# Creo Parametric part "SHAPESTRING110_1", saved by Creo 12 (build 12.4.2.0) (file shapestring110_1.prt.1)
Units: Custom; MM, KILOGRAM, SECS

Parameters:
  PTC_WM_ITERATION = "0"
  PTC_WM_VERSION = "-.0"
  PTC_WM_LIFECYCLE_STATE = "In Work"
  PTC_WM_LIFECYCLE = "MO_CADDocument"
  PTC_WM_CREATED_BY = "Maximilian Roepper (Z0017RMS: MO)"
  PTC_WM_CREATED_ON = "18-Sep-26 11:36:42 AM"
  PTC_WM_MODIFIED_BY = "Maximilian Roepper (Z0017RMS: MO)"
  PTC_WM_MODIFIED_ON = "18-Sep-26 11:36:46 AM"
  PDMLINKNUMBER = "PDM000071455170"
  PTC_WM_NAME = "shapestring110_1.prt"
  PTC_WM_NUMBER = "PDM000071455170"

Other parameters: WEIGHT, WEIGHT_FACTOR, WEIGHT_ADD, _MASS_TEMP, _DIFF_TEMP, MC_ERRORS, SUPPLIER

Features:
  1. coordinate system
  2. datum plane "PRT_YZ"
  3. datum plane "PRT_XY"
  4. datum plane "PRT_XZ"
  5. coordinate system
  6. datum axis
  7. datum axis
  8. datum axis
  9. coordinate system
  10. imported feature

Other named items: PRT, SIEMENS_MO, DRW_VIEW_ORG, PRT_X, PRT_Y, PRT_Z, CS0, ROUGH_GROB

Layers: 00_STD_CSYS-KSYS, 01_STD_PLANES-EBENEN, 02_STD_AXES-ACHSEN, 03_STD_CSYS-KSYS, 24_IMPORT_FEAT-IMPORT_KE, INTFCLR

Surfaces: 1 plane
